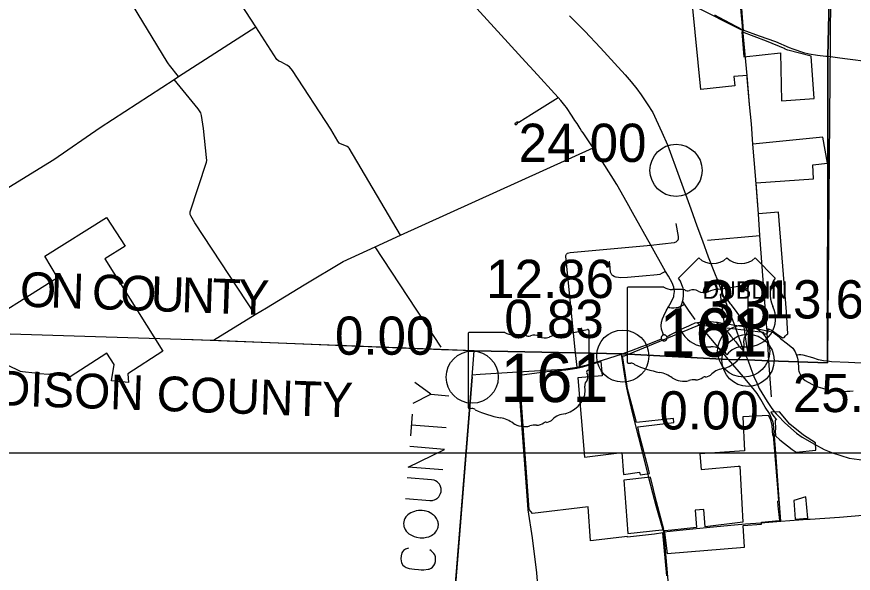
# Model space of a CAD drawing. Extents: x 1659811 to 1934326, y 644115 to 934867.
# Drawn here: x 1757686 to 1781767, y 762046 to 778048 of the extents above; entities that cross this region are included whole.
import ezdxf

# ---------------------------------------------------------------- set-up
doc = ezdxf.new("R2010")
doc.units = 0
for name, color, linetype in [('Default', 7, 'Continuous'), ('GM_X_Adjacent_County', 7, 'Continuous'), ('GM_X_Adjacent_County_Text', 7, 'Continuous'), ('GM_X_City_Street', 7, 'Continuous'), ('GM_X_Corporation', 7, 'Continuous'), ('GM_X_Corporation_Text', 7, 'Continuous'), ('GM_X_County', 7, 'Continuous'), ('GM_X_County_Road', 7, 'Continuous'), ('GM_X_Interchange_Ramps', 7, 'Continuous'), ('GM_X_State_Route', 7, 'Continuous'), ('GM_X_State_Shield', 7, 'Continuous'), ('GM_X_Township_Road', 7, 'Continuous'), ('GM_X_US_Route', 7, 'Continuous'), ('GM_X_US_Shield', 7, 'Continuous'), ('SC_Scratch1', 7, 'Continuous')]:
    doc.layers.add(name, color=color, linetype=linetype)

msp = doc.modelspace()

# ---------------------------------------------------------------- linework, layer by layer
at = {"layer": 'Default'}
for centre in [(1776664, 773631), (1778612, 768434), (1775131, 768290), (1775131, 768290), (1778737, 768169), (1778737, 768169), (1770797, 767685), (1770797, 767685)]:
    msp.add_circle(centre, 750, dxfattribs=at)
at = {"layer": 'GM_X_Adjacent_County'}
for p, q in [((1781136, 781321), (1781021, 768152)), ((1770854, 768445), (1762519, 768766))]:
    msp.add_line(p, q, dxfattribs=at)
at = {"layer": 'GM_X_Adjacent_County_Text'}
for p, q in [((1770794, 767696), (1769899, 756607)), ((1769605, 767193), (1770123, 767151)), ((1769026, 766000), (1769076, 766620)), ((1769052, 766314), (1770048, 766233))]:
    msp.add_line(p, q, dxfattribs=at)
for points in [[(1769102, 766933), (1769605, 767193), (1769150, 767530)], [(1769950, 765017), (1768954, 765097), (1769998, 765605), (1769001, 765686)], [(1768881, 764195), (1769579, 764138), (1769651, 764140), (1769675, 764146), (1769715, 764159), (1769748, 764172), (1769781, 764193), (1769798, 764207), (1769807, 764215), (1769833, 764244), (1769850, 764266), (1769869, 764297), (1769888, 764342), (1769900, 764389), (1769903, 764436), (1769899, 764484), (1769894, 764516), (1769874, 764565), (1769854, 764606), (1769825, 764640), (1769788, 764674), (1769743, 764702), (1769705, 764720), (1769627, 764735), (1768929, 764791)], [(1768826, 763417), (1768832, 763393), (1768838, 763369), (1768858, 763327), (1768872, 763303), (1768900, 763261), (1768929, 763227), (1768944, 763210), (1768973, 763184), (1769048, 763138), (1769124, 763101), (1769194, 763079), (1769295, 763063), (1769406, 763062), (1769486, 763079), (1769551, 763098), (1769583, 763111), (1769624, 763131), (1769666, 763160), (1769692, 763181), (1769717, 763203), (1769743, 763232), (1769770, 763270), (1769807, 763338), (1769818, 763376), (1769824, 763455), (1769819, 763487), (1769814, 763519), (1769801, 763559), (1769781, 763601), (1769767, 763625), (1769753, 763650), (1769731, 763676), (1769702, 763702), (1769680, 763719), (1769657, 763737), (1769635, 763754), (1769590, 763782), (1769537, 763810), (1769475, 763831), (1769421, 763843), (1769413, 763844), (1769358, 763848), (1769311, 763852), (1769248, 763849), (1769184, 763838), (1769135, 763826), (1769079, 763807), (1769030, 763788), (1768979, 763752), (1768945, 763723), (1768911, 763694), (1768885, 763665), (1768858, 763620), (1768839, 763574), (1768827, 763528), (1768822, 763473), (1768826, 763417)], [(1768963, 762766), (1768874, 762734), (1768823, 762698), (1768789, 762662), (1768770, 762632), (1768748, 762546), (1768741, 762460), (1768763, 762348), (1768805, 762281), (1768842, 762247), (1768894, 762211), (1768979, 762180), (1769135, 762160), (1769253, 762150), (1769331, 762144), (1769403, 762146), (1769530, 762160), (1769554, 762165), (1769612, 762192), (1769654, 762221), (1769697, 762272), (1769717, 762318), (1769737, 762380), (1769743, 762450), (1769741, 762522), (1769735, 762546), (1769722, 762578), (1769693, 762612), (1769657, 762655), (1769612, 762690), (1769575, 762717)]]:
    msp.add_lwpolyline(points, dxfattribs=at)
at = {"layer": 'GM_X_City_Street'}
for points in [[(1778587, 777672), (1778487, 778719), (1777576, 782947), (1777365, 783921), (1777309, 784197), (1777205, 785031), (1777094, 786124), (1777069, 786370)], [(1778717, 776294), (1778712, 776354), (1778587, 777672)], [(1778587, 777672), (1779055, 777502), (1779527, 777332), (1779924, 777165), (1780026, 777121), (1780331, 777020), (1780500, 776983), (1780741, 776947), (1780979, 776917), (1781034, 776910)], [(1781034, 776910), (1781525, 776843), (1782284, 776747), (1783301, 776608), (1783588, 776571), (1784196, 776473)], [(1778179, 768197), (1777315, 769219)], [(1779340, 768157), (1779296, 768823), (1779287, 768930), (1779287, 768967)], [(1779341, 769009), (1779415, 768992), (1779466, 768966), (1779559, 768901), (1779671, 768796), (1779873, 768642), (1780023, 768515), (1780091, 768416), (1780134, 768315), (1780161, 768322)], [(1779493, 766103), (1779484, 766221), (1779471, 766340), (1779453, 766411), (1779385, 766572), (1779352, 766635), (1779235, 766821), (1779105, 767038), (1778997, 767211), (1778926, 767307), (1778839, 767419), (1778606, 767697), (1778179, 768197)], [(1780134, 768315), (1780165, 768226), (1780182, 768130)], [(1780161, 768322), (1780204, 768334), (1780259, 768336), (1780313, 768331), (1780595, 768246), (1780755, 768196), (1780813, 768181), (1780912, 768164), (1781021, 768152)], [(1779414, 767119), (1779340, 768157)], [(1780182, 768130), (1780186, 767940), (1780191, 767900), (1780199, 767860), (1780209, 767831), (1780225, 767791), (1780264, 767716), (1780328, 767640), (1780383, 767593), (1780464, 767541), (1780593, 767477), (1780746, 767411), (1780882, 767365), (1780980, 767338), (1781089, 767315), (1781178, 767298), (1781275, 767287), (1781420, 767277), (1781586, 767278), (1781671, 767283), (1781767, 767294)], [(1781021, 768152), (1781136, 768138), (1781634, 768114), (1782186, 768090)], [(1779685, 763542), (1779637, 764172), (1779545, 765387), (1779493, 766103)], [(1775876, 764825), (1775871, 764848), (1775850, 764928)], [(1780526, 763602), (1781375, 763657), (1782825, 763782), (1783060, 763799), (1783527, 763834), (1784109, 763878), (1784225, 763888), (1784256, 763891)], [(1779104, 763498), (1779685, 763542), (1780457, 763598), (1780526, 763602)], [(1776894, 757007), (1776536, 760730), (1776379, 762498), (1776312, 763238), (1776297, 763289)]]:
    msp.add_lwpolyline(points, dxfattribs=at)
at = {"layer": 'GM_X_Corporation'}
for points in [[(1776402, 761968), (1776281, 763207), (1776046, 763174), (1775267, 763080), (1775267, 763099), (1774207, 762980), (1774134, 763952), (1772529, 763765), (1772435, 763880), (1772154, 767744), (1772941, 767852), (1773496, 767895), (1773812, 767946), (1773981, 767984), (1774140, 768026), (1774502, 768137), (1774541, 767725), (1773835, 767662), (1774031, 765380), (1775103, 765517), (1775155, 764887), (1775613, 764948), (1775632, 764875), (1775901, 764913), (1775868, 765038), (1775612, 766018), (1775562, 766261), (1776602, 766385), (1776595, 766499), (1775530, 766385), (1775389, 766892), (1775267, 767351), (1775201, 767808), (1775125, 768301), (1775186, 768299), (1777296, 769167), (1777365, 769179), (1778041, 769112), (1779178, 768980), (1779186, 768933), (1779291, 768930), (1779312, 768982), (1779321, 769021), (1779329, 769061), (1779309, 769075), (1779349, 769065), (1779409, 769034), (1779471, 768997), (1779544, 768942), (1779731, 768815), (1779777, 768829), (1779819, 768873), (1779857, 768907), (1779885, 768930), (1779843, 769567), (1779616, 772429), (1779035, 772377), (1778973, 773273), (1780624, 773390), (1780602, 773789), (1781025, 773834), (1780894, 774583), (1778880, 774385), (1778835, 774970), (1778780, 775529), (1778712, 776354), (1778326, 776325), (1778354, 776062), (1777374, 775955), (1777143, 778385), (1778610, 777639), (1778533, 778680)], [(1776402, 761968), (1776281, 763207), (1776046, 763174), (1775267, 763080), (1775267, 763099), (1774207, 762980), (1774134, 763952), (1772529, 763765), (1772435, 763880), (1772154, 767744), (1772941, 767852), (1773496, 767895), (1773812, 767946), (1773981, 767984), (1774140, 768026), (1774502, 768137), (1774541, 767725), (1773835, 767662), (1774031, 765380), (1775103, 765517), (1775155, 764887), (1775613, 764948), (1775632, 764875), (1775901, 764913), (1775868, 765038), (1775612, 766018), (1775562, 766261), (1776602, 766385), (1776595, 766499), (1775530, 766385), (1775389, 766892), (1775267, 767351), (1775201, 767808), (1775125, 768301), (1775186, 768299), (1777296, 769167), (1777365, 769179), (1778041, 769112), (1779178, 768980), (1779186, 768933), (1779291, 768930), (1779312, 768982), (1779321, 769021), (1779329, 769061), (1779309, 769075), (1779349, 769065), (1779409, 769034), (1779471, 768997), (1779544, 768942), (1779731, 768815), (1779777, 768829), (1779819, 768873), (1779857, 768907), (1779885, 768930), (1779843, 769567), (1779616, 772429), (1779035, 772377), (1778973, 773273), (1780624, 773390), (1780602, 773789), (1781025, 773834), (1780894, 774583), (1778880, 774385), (1778835, 774970), (1778780, 775529), (1778712, 776354), (1778326, 776325), (1778354, 776062), (1777374, 775955), (1777143, 778385), (1778610, 777639), (1778533, 778680)], [(1756324, 768958), (1758862, 770549), (1758491, 771166), (1760272, 772279), (1760808, 771453), (1760226, 771091), (1761888, 768431), (1760888, 767783), (1760902, 767530), (1760417, 767575), (1760493, 768046), (1760284, 768371), (1759227, 767691), (1758902, 767734), (1758675, 767783), (1758612, 767757), (1758330, 767784), (1758211, 767799), (1757849, 767837), (1757798, 767848), (1757778, 767859), (1757443, 768021)]]:
    msp.add_lwpolyline(points, dxfattribs=at)
for points in [[(1778615, 776896), (1779670, 777013), (1779697, 775634), (1780643, 775701), (1780556, 776916), (1779886, 777084), (1779855, 777098), (1779803, 777112), (1779802, 777121), (1779268, 777344), (1778560, 777617)], [(1778615, 776896), (1779670, 777013), (1779697, 775634), (1780643, 775701), (1780556, 776916), (1779886, 777084), (1779855, 777098), (1779803, 777112), (1779802, 777121), (1779268, 777344), (1778560, 777617)], [(1777350, 765480), (1777390, 765033), (1778456, 765121), (1778497, 765124), (1778588, 763518), (1777500, 763383), (1777464, 763881), (1777215, 763863), (1777251, 763358), (1776548, 763289), (1776325, 763267), (1776334, 763222), (1776405, 762617), (1778638, 762800), (1778601, 763421), (1779128, 763459), (1779121, 763518), (1779630, 763563), (1779650, 763567), (1779608, 763988), (1779595, 764118), (1779623, 764127), (1779603, 764375), (1779472, 766012), (1779452, 766010), (1779430, 766292), (1779392, 766458), (1779331, 766585), (1778592, 766543), (1778640, 765564)], [(1777350, 765480), (1777390, 765033), (1778456, 765121), (1778497, 765124), (1778588, 763518), (1777500, 763383), (1777464, 763881), (1777215, 763863), (1777251, 763358), (1776548, 763289), (1776325, 763267), (1776334, 763222), (1776405, 762617), (1778638, 762800), (1778601, 763421), (1779128, 763459), (1779121, 763518), (1779630, 763563), (1779650, 763567), (1779608, 763988), (1779595, 764118), (1779623, 764127), (1779603, 764375), (1779472, 766012), (1779452, 766010), (1779430, 766292), (1779392, 766458), (1779331, 766585), (1778592, 766543), (1778640, 765564)], [(1779526, 765996), (1779649, 765886), (1780007, 765600), (1780127, 765528), (1780688, 765588), (1780677, 765797), (1780336, 766018), (1779945, 766331), (1779640, 766689), (1779392, 766675), (1779449, 766592), (1779558, 766458), (1779517, 766446), (1779531, 766180), (1779519, 766152)], [(1779526, 765996), (1779649, 765886), (1780007, 765600), (1780127, 765528), (1780688, 765588), (1780677, 765797), (1780336, 766018), (1779945, 766331), (1779640, 766689), (1779392, 766675), (1779449, 766592), (1779558, 766458), (1779517, 766446), (1779531, 766180), (1779519, 766152)], [(1775930, 764813), (1775164, 764720), (1775275, 763188), (1776254, 763296), (1776316, 763302), (1776105, 764098)], [(1775930, 764813), (1775164, 764720), (1775275, 763188), (1776254, 763296), (1776316, 763302), (1776105, 764098)], [(1780404, 764245), (1780055, 764138), (1780095, 763598), (1780455, 763628)], [(1780404, 764245), (1780055, 764138), (1780095, 763598), (1780455, 763628)]]:
    msp.add_lwpolyline(points, close=True, dxfattribs=at)
at = {"layer": 'GM_X_County'}
for points in [[(1781136, 781321), (1781034, 776910), (1781038, 774723), (1781021, 768152), (1781021, 768101), (1780182, 768130), (1779340, 768157), (1778733, 768178), (1778179, 768197), (1775112, 768352), (1773771, 768383), (1770854, 768445), (1769914, 768473), (1763343, 768740), (1757498, 768922)], [(1769596, 752863), (1769725, 754457), (1769778, 755119), (1769899, 756607), (1769900, 756629), (1770794, 767696), (1770854, 768445), (1773771, 768383), (1775112, 768352), (1778179, 768197), (1778733, 768178), (1779340, 768157), (1780182, 768130), (1781021, 768101), (1781021, 768152), (1781038, 774723), (1781034, 776910), (1781136, 781321), (1783093, 781151)]]:
    msp.add_lwpolyline(points, dxfattribs=at)
at = {"layer": 'GM_X_County_Road'}
for points in [[(1764567, 777757), (1763540, 779337), (1763518, 779375), (1763506, 779412), (1763499, 779458), (1763505, 779496), (1763524, 779542), (1763552, 779582), (1763603, 779626), (1763821, 779760), (1764499, 780186), (1764546, 780214), (1764616, 780259), (1765224, 780551), (1765262, 780565), (1765306, 780574), (1768412, 781054)], [(1762339, 776327), (1762083, 776655), (1762057, 776693), (1762015, 776752), (1759884, 780255), (1759662, 780605)], [(1776602, 770034), (1776616, 770144), (1776601, 770271), (1776549, 770393), (1776444, 770592), (1776364, 770727), (1775940, 771484), (1775407, 772421), (1775259, 772693), (1774963, 773229), (1774801, 773485), (1774545, 773878), (1774277, 774279), (1774144, 774476), (1773988, 774713), (1773948, 774772), (1773908, 774831), (1773815, 774976), (1773754, 775065), (1773676, 775185), (1773507, 775437), (1773466, 775494), (1773425, 775548), (1773352, 775636), (1773275, 775722), (1772576, 776490), (1772333, 776755), (1770526, 778737)], [(1777771, 778103), (1778062, 777945), (1778390, 777779), (1778587, 777672)], [(1755151, 770993), (1755084, 771381), (1755081, 771445), (1755098, 771515), (1755137, 771580), (1755368, 771817), (1755876, 772185), (1756293, 772435), (1757582, 773220), (1758755, 773947), (1760089, 774866), (1762214, 776244), (1762339, 776327), (1764567, 777757)], [(1779287, 769021), (1779267, 769209), (1779076, 771761), (1779035, 772377), (1778956, 773487), (1778880, 774385), (1778835, 774970), (1778780, 775529), (1778717, 776294)], [(1768002, 771434), (1768732, 771763), (1774277, 774279)], [(1769900, 768544), (1768002, 771434)], [(1776299, 768895), (1776293, 768926), (1776245, 769060), (1776237, 769161), (1776246, 769263), (1776276, 769358), (1776314, 769444), (1776383, 769587), (1776447, 769703), (1776528, 769837), (1776598, 770005), (1776602, 770034)], [(1777315, 769219), (1777281, 769260)], [(1777823, 769266), (1777861, 769262), (1777953, 769247), (1778049, 769234), (1778346, 769181), (1778622, 769146), (1778980, 769079)], [(1778980, 769079), (1779287, 769021)], [(1779287, 768967), (1779287, 769021)], [(1779287, 769021), (1779341, 769009)], [(1775850, 764928), (1775594, 765946), (1775415, 766673), (1775278, 767240), (1775242, 767424), (1775205, 767658), (1775094, 768346)], [(1772766, 760732), (1772657, 762055), (1772537, 763066), (1772406, 763865), (1772376, 764274), (1772178, 766985), (1772115, 767838)], [(1776297, 763289), (1776096, 763986), (1775996, 764347), (1775876, 764825)], [(1776312, 763238), (1776864, 763293), (1777637, 763368), (1778352, 763436), (1778667, 763465), (1779104, 763498)]]:
    msp.add_lwpolyline(points, dxfattribs=at)
at = {"layer": 'GM_X_Interchange_Ramps'}
for points in [[(1778000, 770085), (1777932, 770061), (1777954, 769927), (1777975, 769811), (1777993, 769667), (1778045, 769276), (1778049, 769234)], [(1778622, 769146), (1778617, 769179), (1778615, 769235), (1778609, 769268), (1778598, 769301), (1778581, 769332), (1778562, 769358), (1778287, 769725), (1778251, 769771), (1778234, 769797), (1778194, 769847), (1778130, 769937), (1778066, 769911)], [(1778049, 769234), (1778053, 769202), (1778066, 769146), (1778076, 769116), (1778082, 769096), (1778100, 769050), (1778091, 769041)], [(1778665, 768321), (1778737, 768355), (1778713, 768524), (1778698, 768657), (1778666, 768848), (1778625, 769118), (1778622, 769146)]]:
    msp.add_lwpolyline(points, dxfattribs=at)
at = {"layer": 'GM_X_State_Route'}
for points in [[(1776494, 768902), (1776629, 768973), (1776792, 769052), (1776901, 769107), (1777029, 769163)], [(1777029, 769163), (1777095, 769192), (1777211, 769243), (1777281, 769260)], [(1777281, 769260), (1777394, 769278), (1777484, 769288), (1777571, 769291), (1777670, 769285), (1777823, 769266)], [(1777823, 769266), (1777871, 769232), (1777893, 769214)], [(1777893, 769214), (1777937, 769177), (1778023, 769103), (1778091, 769041), (1778137, 768994), (1778246, 768862), (1778383, 768696), (1778473, 768572), (1778607, 768443)], [(1775679, 768563), (1775848, 768626), (1776243, 768783)], [(1776396, 768855), (1776388, 768867), (1776379, 768877), (1776369, 768885), (1776359, 768890), (1776347, 768895), (1776333, 768898), (1776319, 768898), (1776308, 768898), (1776299, 768895), (1776286, 768890), (1776276, 768884), (1776269, 768880), (1776262, 768873), (1776255, 768865), (1776248, 768854), (1776242, 768842), (1776239, 768831), (1776238, 768820), (1776238, 768807), (1776239, 768795), (1776241, 768787), (1776243, 768783)], [(1776243, 768783), (1776248, 768772), (1776253, 768764), (1776261, 768755), (1776268, 768748), (1776277, 768742), (1776287, 768736), (1776294, 768733), (1776304, 768730), (1776315, 768729), (1776322, 768728), (1776335, 768729), (1776346, 768732), (1776357, 768735), (1776367, 768741), (1776375, 768746), (1776381, 768752), (1776387, 768758), (1776394, 768767), (1776400, 768779), (1776404, 768788), (1776406, 768801), (1776407, 768813), (1776406, 768826), (1776402, 768841), (1776397, 768854), (1776396, 768855)], [(1776396, 768855), (1776448, 768877), (1776494, 768902)], [(1775112, 768352), (1775218, 768389), (1775384, 768452), (1775679, 768563)], [(1770782, 767754), (1771024, 767766), (1772115, 767838), (1772909, 767883), (1773429, 767916), (1773615, 767939), (1773818, 767968), (1774109, 768040), (1774573, 768184), (1775094, 768346), (1775112, 768352)]]:
    msp.add_lwpolyline(points, dxfattribs=at)
at = {"layer": 'GM_X_State_Shield'}
for p, q in [((1775259, 770237), (1775259, 768124)), ((1776313, 770273), (1775294, 770273)), ((1778740, 769220), (1778740, 770326)), ((1778739, 769221), (1778740, 769220)), ((1770680, 768934), (1770680, 766820)), ((1771733, 768970), (1770714, 768970)), ((1774160, 767917), (1774160, 769022)), ((1774160, 767917), (1774160, 767917))]:
    msp.add_line(p, q, dxfattribs=at)
for centre, major_axis, start_param, end_param in [((1777500, 773155), (3691, 0), 4.814394, 5.042369), ((1778701, 770330), (38.7, 0), 6.141152, 7.989035), ((1775299, 770242), (40.3, 0), 1.712693, 3.28349), ((1776556, 770519), (391, 0), 4.042523, 4.731795), ((1776685, 769087), (1404, 0), 1.404758, 1.657858), ((1777004, 770253), (113, 0), 3.836095, 5.185415), ((1777170, 770008), (235, 0), 0.950623, 2.079405), ((1777472, 770343), (282, 0), 4.081561, 5.145723), ((1777971, 769628), (743, 0), 1.699011, 2.107814), ((1778731, 769139), (60, 0), 1.883978, 3.671073), ((1778698, 769216), (41.5, 0), 5.05454, 6.418171), ((1770719, 768938), (40.3, 0), 1.712693, 3.28349), ((1771976, 769215), (391, 0), 4.042523, 4.731795), ((1772106, 767784), (1404, 0), 1.404758, 1.657858), ((1773391, 768325), (743, 0), 1.699011, 2.107814), ((1772920, 771851), (3691, 0), 4.814394, 5.042369), ((1774121, 769027), (38.7, 0), 6.141152, 7.989035), ((1778349, 768999), (360, 0), 5.934695, 6.695948), ((1772424, 768949), (113, 0), 3.836095, 5.185415), ((1772590, 768705), (235, 0), 0.950623, 2.079405), ((1772893, 769040), (282, 0), 4.081561, 5.145723), ((1777707, 768617), (923, 0), 5.101752, 6.440018), ((1778878, 768758), (262, 0), 2.387724, 3.262537), ((1775300, 768119), (40.7, 0), 3.00124, 4.508301), ((1775306, 768335), (310, 0), 4.665946, 4.897461), ((1775369, 768002), (112, 0), 0.519207, 1.627899), ((1776782, 769901), (2665, 0), 4.195997, 4.488961), ((1774151, 767836), (60, 0), 1.883978, 3.671073), ((1773770, 767696), (360, 0), 5.934695, 6.695948), ((1774119, 767913), (41.5, 0), 5.05454, 6.418171), ((1775988, 767174), (834, 0), 0.823519, 1.323587), ((1777455, 767919), (298, 0), 4.937069, 5.64225), ((1778096, 767531), (506, 0), 1.647645, 2.488434), ((1774299, 767454), (262, 0), 2.387724, 3.262537), ((1776890, 767991), (529, 0), 4.026481, 4.996735), ((1777195, 767261), (435, 0), 1.495662, 1.94098), ((1777234, 767833), (282, 0), 4.691044, 5.507374), ((1777489, 767629), (79.4, 0), 1.147584, 2.315152), ((1773127, 767314), (923, 0), 5.101752, 6.440018), ((1770720, 766816), (40.7, 0), 3.00124, 4.508301), ((1770726, 767032), (310, 0), 4.665946, 4.897461), ((1770790, 766698), (112, 0), 0.519207, 1.627899), ((1772203, 768597), (2665, 0), 4.195997, 4.488961), ((1771408, 765871), (834, 0), 0.823519, 1.323587), ((1773516, 766227), (506, 0), 1.647645, 2.488434), ((1772310, 766688), (529, 0), 4.026481, 4.996735), ((1772616, 765957), (435, 0), 1.495662, 1.94098), ((1772654, 766530), (282, 0), 4.691044, 5.507374), ((1772909, 766325), (79.4, 0), 1.147584, 2.315152), ((1772876, 766616), (298, 0), 4.937069, 5.64225)]:
    msp.add_ellipse(centre, major_axis=major_axis, ratio=0.8, start_param=start_param, end_param=end_param, dxfattribs=at)
at = {"layer": 'GM_X_Township_Road'}
for points in [[(1768732, 771763), (1767259, 774266), (1767237, 774286), (1767197, 774314), (1766991, 774400), (1766963, 774416), (1766931, 774472), (1766723, 774811), (1765624, 776498), (1765537, 776605), (1765461, 776659), (1765393, 776694), (1765284, 776749), (1765234, 776774), (1765171, 776816), (1764567, 777757)], [(1764554, 769483), (1762816, 772121), (1762693, 772328), (1762675, 772366), (1762683, 772434), (1763149, 773866), (1763157, 773918), (1763147, 774001), (1763066, 774834), (1763007, 775206), (1762987, 775287), (1762908, 775402), (1762214, 776244)], [(1772142, 775020), (1772503, 775249), (1773275, 775722)], [(1772118, 775022), (1772086, 775017), (1772058, 775004), (1772040, 774992), (1772029, 774982), (1772028, 774966), (1772035, 774951), (1772049, 774949), (1772068, 774954), (1772091, 774973), (1772119, 775005), (1772142, 775020)], [(1775940, 771484), (1776607, 771555), (1776618, 771555), (1776640, 771562), (1776673, 771579), (1776690, 771593), (1776707, 771612), (1776722, 771637), (1776731, 771660), (1776736, 771680), (1776737, 771707), (1776735, 771730), (1776669, 772101)], [(1777572, 771626), (1779076, 771761)], [(1765962, 770335), (1767080, 771012), (1768002, 771434)], [(1773771, 768383), (1773495, 771157), (1773495, 771183), (1773507, 771225), (1773541, 771253), (1773613, 771265), (1775940, 771484)], [(1776364, 770727), (1776267, 770671), (1776200, 770641), (1776123, 770625), (1776030, 770617), (1775801, 770600), (1775269, 770547), (1775079, 770545), (1774945, 770559), (1774930, 770561), (1774904, 770567), (1774880, 770577), (1774838, 770604), (1774814, 770631), (1774794, 770664), (1774781, 770705), (1774747, 771022)], [(1764879, 769680), (1765962, 770335)], [(1777216, 769342), (1777025, 769611), (1776910, 769785), (1776847, 769882)], [(1763349, 768744), (1764554, 769483), (1764879, 769680)], [(1776447, 769703), (1776481, 769691), (1776533, 769681), (1776558, 769678), (1776597, 769682), (1776726, 769696), (1776750, 769701), (1776804, 769724), (1776883, 769768), (1776910, 769785)], [(1773818, 767968), (1773771, 768383)]]:
    msp.add_lwpolyline(points, dxfattribs=at)
at = {"layer": 'GM_X_US_Route'}
for points in [[(1773598, 778078), (1774035, 777630), (1774486, 777156), (1774892, 776712), (1775198, 776382), (1775374, 776176), (1775535, 775977), (1775665, 775800), (1775834, 775547), (1775993, 775293), (1776097, 775080), (1776256, 774732), (1776416, 774364), (1777089, 772524), (1777268, 772034), (1777426, 771605), (1777588, 771145), (1777732, 770782), (1777892, 770375), (1778000, 770085), (1778066, 769911), (1778346, 769181), (1778372, 769109)], [(1778372, 769109), (1778405, 769014)], [(1778405, 769014), (1778607, 768443)], [(1778607, 768443), (1778665, 768321), (1778733, 768178)], [(1778733, 768178), (1778817, 767930), (1778905, 767705), (1778988, 767518), (1779062, 767362), (1779287, 766981), (1779404, 766816), (1779481, 766710)], [(1779481, 766710), (1779494, 766693), (1779551, 766633)], [(1779551, 766633), (1779597, 766584), (1779797, 766367), (1780136, 766075), (1780293, 765955), (1780653, 765760), (1780928, 765603), (1781172, 765512), (1781651, 765359), (1781933, 765316), (1782177, 765280), (1782448, 765261), (1782979, 765256)]]:
    msp.add_lwpolyline(points, dxfattribs=at)
at = {"layer": 'GM_X_US_Shield'}
for p, q in [((1777318, 771113), (1776738, 770533)), ((1779522, 770533), (1778942, 771113)), ((1777550, 768561), (1777666, 768561)), ((1778594, 768561), (1778710, 768561))]:
    msp.add_line(p, q, dxfattribs=at)
for centre, radius, start, end in [((1777724, 771528), 580, 225.573, 314.427), ((1778536, 771528), 580, 225.573, 314.427), ((1776072, 770068), 812, 334.5471, 35.0009), ((1780187, 770068), 812, 144.9991, 205.4529), ((1777541, 769373), 812, 154.8319, 270.6383), ((1778719, 769373), 812, 269.3617, 25.1681), ((1777666, 767981), 580, 36.8699, 90), ((1778594, 767981), 580, 90, 143.1301)]:
    msp.add_arc(centre, radius, start, end, dxfattribs=at)
at = {"layer": 'SC_Scratch1'}
msp.add_lwpolyline([(1729596, 899996), (1925846, 899996), (1925846, 765496), (1729596, 765496)], close=True, dxfattribs=at)

# ---------------------------------------------------------------- texts
at = {"layer": 'Default'}
for s, p in [('24.00', (1772133, 773873)), ('12.86', (1771200, 769960)), ('13.67', (1779215, 769372)), ('0.83', (1771722, 768810)), ('0.00', (1766846, 768328)), ('25.11', (1780028, 766680)), ('0.00', (1776185, 766180))]:
    msp.add_text(s, height=1100, dxfattribs=at).set_placement(p)
at = {"layer": 'GM_X_Adjacent_County_Text'}
for s, rotation, p in [('O', 358.1324, (1757766, 769714)), ('N', 358.0802, (1758648, 769685)), ('C', 358.0225, (1759836, 769645)), ('O', 358.018, (1760650, 769617)), ('U', 358.0179, (1761532, 769586)), ('N', 358.0179, (1762415, 769556)), ('T', 358.0181, (1763297, 769525)), ('Y', 358.0181, (1764043, 769499)), ('MADISON COUNTY', 358.0066, (1755091, 766949))]:
    msp.add_text(s, height=1000, rotation=rotation, dxfattribs=at).set_placement(p)
at = {"layer": 'GM_X_Corporation_Text'}
msp.add_text('DUBLIN', height=500, rotation=0, dxfattribs=at).set_placement((1777422, 769938))
at = {"layer": 'GM_X_State_Shield'}
for p in [(1776190, 768273), (1771610, 766969)]:
    msp.add_text('161', height=1392.2, dxfattribs=at).set_placement(p)
at = {"layer": 'GM_X_US_Shield'}
msp.add_text('33', height=1392.2, dxfattribs=at).set_placement((1777337, 769083))

doc.saveas('drawing.dxf')
